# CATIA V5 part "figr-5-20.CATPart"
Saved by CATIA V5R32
Part number: Part1
Bounding box of the stored display mesh (mm): x -89.73 to 98.105, y -54.237 to 64.207, z 0 to 103
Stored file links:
  D:\PROJECTS\Project 2022\CATIA V5 6R 2022\Resources\Part Files\c05_catia_v5_6r2022_prt\figr-5-20.CATPart
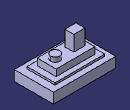
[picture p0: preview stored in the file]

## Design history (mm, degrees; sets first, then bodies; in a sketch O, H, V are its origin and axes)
Body1 (main body)
  Sketch1 on xy-plane, origin (0, 0, 0), H (1, 0, 0), V (0, 1, 0)
    line L1 (-89.7304, 64.2071) -> (98.1053, 64.2071)
    line L2 (98.1053, 64.2071) -> (98.1053, -54.2371)
    line L3 (98.1053, -54.2371) -> (-89.7304, -54.2371)
    line L4 (-89.7304, -54.2371) -> (-89.7304, 64.2071)
    line L5 (-72.4817, 47.8756) -> (77.1251, 47.8756)
    line L6 (77.1251, 47.8756) -> (77.1251, -36.7263)
    line L7 (77.1251, -36.7263) -> (-72.4817, -36.7263)
    line L8 (-72.4817, -36.7263) -> (-72.4817, 47.8756)
    line L9 (-57.1864, 33.5363) -> (59.44, 33.5363)
    line L10 (59.44, 33.5363) -> (59.44, -23.821)
    line L11 (59.44, -23.821) -> (-57.1864, -23.821)
    line L12 (-57.1864, -23.821) -> (-57.1864, 33.5363)
    circle A1 centre (34.1072, 5.3356) radius 13.9353
    line L13 (-44.759, 16.3291) -> (-11.3006, 16.3291)
    line L14 (-11.3006, 16.3291) -> (-11.3006, -10.9156)
    line L15 (-11.3006, -10.9156) -> (-44.759, -10.9156)
    line L16 (-44.759, -10.9156) -> (-44.759, 16.3291)
    horizontal: L1 H, L3 H, L5 H, L7 H, L9 H, L11 H, L13 H, L15 H
    vertical: L4 V, L6 V, L8 V, L10 V, L12 V, L14 V, L16 V
  MultiPad1: profile Sketch1, domains (length 103; length 57; length 0 / length -37; length 31; length 71)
